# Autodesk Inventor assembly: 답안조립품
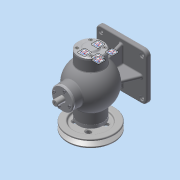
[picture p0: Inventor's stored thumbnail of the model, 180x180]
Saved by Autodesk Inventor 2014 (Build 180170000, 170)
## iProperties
Created: 2017-01
Part Number: 답안조립품
Document SubType Name: Assembly
Designer: ksu
Author: ksu
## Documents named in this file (19)
- C:\Users\ksu\Desktop\470118V1001\답안조립품.iam
- C:\Users\ksu\Desktop\470118V1001\1본체.ipt
- C:\Users\ksu\Desktop\470118V1001\470118V1001\편심축.ipt
- C:\Users\ksu\Desktop\470118V1001\470118V1001\키 4 x 4 x 12.ipt
- C:\Users\ksu\Desktop\470118V1001\470118V1001\V-벨트풀리.ipt
- C:\Users\ksu\Desktop\470118V1001\470118V1001\너트 M8.ipt
- C:\Users\ksu\Desktop\470118V1001\470118V1001\부시.ipt
- C:\Users\ksu\Desktop\470118V1001\470118V1001\베어링- 6202.ipt
- KS B 2023 - 6202 - 15 x 35 x 11 - 7.8.ipt
- C:\Users\ksu\Desktop\470118V1001\470118V1001\앞커버.ipt
- C:\Users\ksu\Desktop\470118V1001\470118V1001\오일실 15 30 7.ipt
- C:\Users\ksu\Desktop\470118V1001\470118V1001\볼트 M4 x 16.ipt
- C:\Users\ksu\Desktop\470118V1001\470118V1001\상부커버.ipt
- C:\Users\ksu\Desktop\470118V1001\470118V1001\볼트 M4 x 12.ipt
- C:\Users\ksu\Desktop\470118V1001\470118V1001\슬라이드.ipt
- C:\Users\ksu\Desktop\470118V1001\470118V1001\뒤커버.ipt
- C:\Users\ksu\Desktop\470118V1001\470118V1001\멈춤링- 15 x 1.ipt
- C:\Users\ksu\Desktop\470118V1001\470118V1001\멈춤링- 35x1.6.ipt
- KS B 1336 - 35x1.6.ipt
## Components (17 placed, 6 different names)
1. 1본체:1 — Mate:4, Insert:22, Insert:23, Mate:5, Insert:24
2. V-벨트풀리:1 — Insert:1, Insert:2
3. KS B 2023 - 6202 - 15 x 35 x 11 - 7.8:1 — Insert:4
4. ISO 4762 M4 x 16:1 — Insert:7
5. ISO 4762 M4 x 16:2 — Insert:8
6. ISO 4762 M4 x 16:3 — Insert:9
7. ISO 4762 M4 x 16:4 — Insert:6
8. KS B 1021 - 에 따름 ISO 1207 - 미터 A  M 4 x 12:1 — Insert:10
9. KS B 1021 - 에 따름 ISO 1207 - 미터 A  M 4 x 12:2 — Insert:11
10. KS B 1021 - 에 따름 ISO 1207 - 미터 A  M 4 x 12:3 — Insert:12
11. KS B 1021 - 에 따름 ISO 1207 - 미터 A  M 4 x 12:4 — Insert:13
12. ISO 4762 M4 x 16:5 — Insert:17
13. ISO 4762 M4 x 16:6 — Insert:15
14. ISO 4762 M4 x 16:7 — Insert:14
15. ISO 4762 M4 x 16:8 — Insert:16
16. KS B 2023 - 6202 - 15 x 35 x 11 - 7.8:2 — Insert:19, Insert:20, Insert:21
17. KS B 1336 - 35x1.6:1 — Insert:20
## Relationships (23: Insert 21, Mate 2)
- Mate:4: 1본체:1
- Insert:1: V-벨트풀리:1
- Insert:2: V-벨트풀리:1
- Insert:4: KS B 2023 - 6202 - 15 x 35 x 11 - 7.8:1
- Insert:6: ISO 4762 M4 x 16:4
- Insert:7: ISO 4762 M4 x 16:1
- Insert:8: ISO 4762 M4 x 16:2
- Insert:9: ISO 4762 M4 x 16:3
- Insert:10: KS B 1021 - 에 따름 ISO 1207 - 미터 A  M 4 x 12:1
- Insert:11: KS B 1021 - 에 따름 ISO 1207 - 미터 A  M 4 x 12:2
- Insert:12: KS B 1021 - 에 따름 ISO 1207 - 미터 A  M 4 x 12:3
- Insert:13: KS B 1021 - 에 따름 ISO 1207 - 미터 A  M 4 x 12:4
- Insert:14: ISO 4762 M4 x 16:7
- Insert:15: ISO 4762 M4 x 16:6
- Insert:16: ISO 4762 M4 x 16:8
- Insert:17: ISO 4762 M4 x 16:5
- Insert:19: KS B 2023 - 6202 - 15 x 35 x 11 - 7.8:2
- Insert:20: KS B 2023 - 6202 - 15 x 35 x 11 - 7.8:2 ↔ KS B 1336 - 35x1.6:1
- Insert:21: KS B 2023 - 6202 - 15 x 35 x 11 - 7.8:2
- Insert:22: 1본체:1
- Insert:23: 1본체:1
- Mate:5: 1본체:1
- Insert:24: 1본체:1
